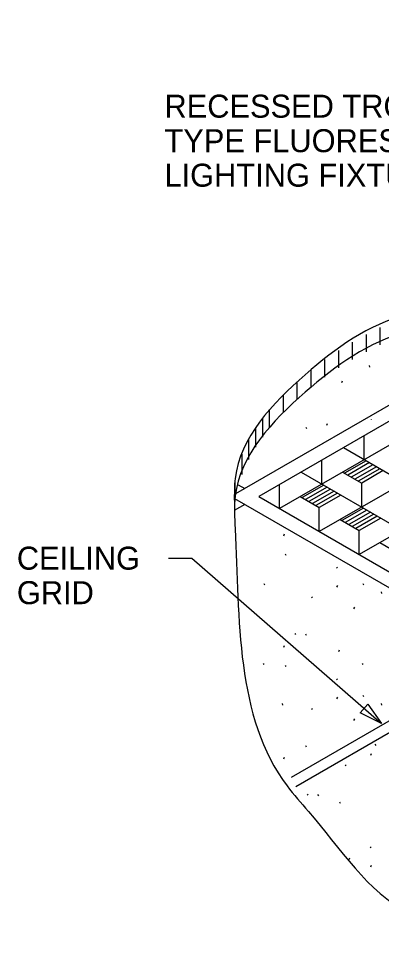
# Model space of a CAD drawing. Extents: x -12191 to -12144.8, y -12274.7 to -12230.3.
# Drawn here: x -12190.98 to -12180.47, y -12256.91 to -12230.27 of the extents above; entities that cross this region are included whole.
import ezdxf

# ---------------------------------------------------------------- set-up
doc = ezdxf.new("R2010")
doc.units = 0
for name, color, linetype in [('G-ANNO-TEXT', 7, 'Continuous'), ('G-DETL-LINE', 7, 'Continuous'), ('G-DETL-OTLN', 7, 'Continuous'), ('G-DETL-PATT', 7, 'Continuous')]:
    doc.layers.add(name, color=color, linetype=linetype)

msp = doc.modelspace()

# ---------------------------------------------------------------- linework, layer by layer
at = {"layer": 'G-ANNO-TEXT'}
for p, q in [((-12186.633, -12245.916), (-12185.966, -12245.916)), ((-12185.966, -12245.916), (-12180.475, -12250.707))]:
    msp.add_line(p, q, dxfattribs=at)
msp.add_lwpolyline([(-12180.867, -12250.143), (-12180.475, -12250.707), (-12181.087, -12250.394)], close=True, dxfattribs=at)
msp.add_lwpolyline([(-12180.867, -12250.143), (-12180.475, -12250.707), (-12181.087, -12250.394)], close=True, dxfattribs=at)
at = {"layer": 'G-DETL-LINE'}
for p, q in [((-12167.216, -12235.118), (-12183.425, -12244.476)), ((-12166.063, -12235.784), (-12182.272, -12245.142)), ((-12164.909, -12236.45), (-12181.118, -12245.808)), ((-12180.972, -12243.06), (-12180.972, -12242.367)), ((-12181.572, -12242.713), (-12174.052, -12247.055)), ((-12182.199, -12243.768), (-12182.199, -12243.075)), ((-12182.799, -12243.422), (-12175.278, -12247.763)), ((-12181.599, -12243.422), (-12181.045, -12243.741)), ((-12180.419, -12243.379), (-12181.045, -12243.741)), ((-12184.621, -12243.786), (-12184.425, -12243.899)), ((-12183.425, -12244.476), (-12183.425, -12243.783)), ((-12181.045, -12244.434), (-12181.045, -12243.741)), ((-12182.825, -12244.13), (-12182.272, -12244.449)), ((-12182.825, -12244.13), (-12182.272, -12244.449)), ((-12181.645, -12244.087), (-12182.272, -12244.449)), ((-12182.272, -12245.142), (-12182.272, -12244.449)), ((-12181.672, -12244.796), (-12181.118, -12245.115)), ((-12181.672, -12244.796), (-12181.118, -12245.115)), ((-12180.492, -12244.753), (-12181.118, -12245.115)), ((-12181.118, -12245.808), (-12181.118, -12245.115)), ((-12180.518, -12245.461), (-12179.965, -12245.781))]:
    msp.add_line(p, q, dxfattribs=at)
for points in [[(-12184.425, -12244.361), (-12184.732, -12244.538)], [(-12183.074, -12252.264), (-12176.905, -12248.702)], [(-12176.605, -12248.876), (-12182.947, -12252.538)]]:
    msp.add_lwpolyline(points, dxfattribs=at)
for points in [[(-12162.525, -12230.863), (-12165.604, -12230.321), (-12169.198, -12231.517), (-12170.826, -12232.527), (-12172.975, -12234.8), (-12175.893, -12236.119), (-12177.556, -12238.172), (-12179.732, -12238.849), (-12182.68, -12240.598), (-12184.707, -12243.604), (-12184.731, -12244.279)], [(-12162.525, -12231.37), (-12165.604, -12230.828), (-12169.198, -12232.024), (-12170.826, -12233.034), (-12172.975, -12235.307), (-12175.893, -12236.626), (-12177.556, -12238.679), (-12179.732, -12239.356), (-12182.68, -12241.105), (-12184.707, -12244.111), (-12184.707, -12245.062), (-12183.203, -12252.517), (-12182.588, -12253.253), (-12179.703, -12256.194), (-12174.789, -12256.716), (-12173.683, -12256.716), (-12171.38, -12255.642), (-12168.063, -12253.372), (-12164.408, -12252.329), (-12160.507, -12251.439), (-12159.14, -12248.077), (-12153.766, -12245.839), (-12151.853, -12243.292), (-12157.417, -12237.797), (-12158.233, -12233.96), (-12159.83, -12232.61), (-12162.157, -12231.504), (-12162.498, -12231.379)]]:
    msp.add_spline(points, degree=3, dxfattribs=at)
at = {"layer": 'G-DETL-OTLN'}
msp.add_lwpolyline([(-12184.723, -12244.189), (-12176.505, -12248.933), (-12159.496, -12239.113), (-12167.816, -12234.31), (-12184.694, -12244.054)], dxfattribs=at)
msp.add_lwpolyline([(-12167.816, -12234.771), (-12184.025, -12244.13), (-12176.505, -12248.471), (-12160.296, -12239.113)], close=True, dxfattribs=at)
at = {"layer": 'G-DETL-PATT'}
for p, q in [((-12180.518, -12239.227), (-12180.518, -12239.734)), ((-12180.918, -12239.432), (-12180.918, -12239.939)), ((-12181.318, -12239.653), (-12181.318, -12240.16)), ((-12181.718, -12239.895), (-12181.718, -12240.402)), ((-12182.118, -12240.163), (-12182.118, -12240.67)), ((-12180.828, -12240.332), (-12180.823, -12240.38)), ((-12182.518, -12240.464), (-12182.518, -12240.971)), ((-12182.918, -12240.803), (-12182.918, -12241.311)), ((-12181.62, -12240.822), (-12181.598, -12240.774)), ((-12183.318, -12241.178), (-12183.318, -12241.696)), ((-12183.718, -12241.608), (-12183.718, -12242.146)), ((-12183.918, -12241.855), (-12183.918, -12242.407)), ((-12180.761, -12241.899), (-12180.757, -12241.889)), ((-12184.118, -12242.136), (-12184.118, -12242.703)), ((-12182.661, -12242.124), (-12182.639, -12242.157)), ((-12182.057, -12242.061), (-12182.035, -12242.013)), ((-12184.318, -12242.468), (-12184.318, -12243.052)), ((-12184.518, -12242.898), (-12184.518, -12243.492)), ((-12180.919, -12243.091), (-12181.545, -12243.452)), ((-12180.819, -12243.148), (-12181.445, -12243.51)), ((-12180.719, -12243.206), (-12181.345, -12243.568)), ((-12180.619, -12243.264), (-12181.245, -12243.626)), ((-12180.519, -12243.322), (-12181.145, -12243.683)), ((-12184.718, -12243.683), (-12184.718, -12244.163)), ((-12182.145, -12243.799), (-12182.772, -12244.16)), ((-12182.045, -12243.856), (-12182.672, -12244.218)), ((-12181.945, -12243.914), (-12182.572, -12244.276)), ((-12181.845, -12243.972), (-12182.472, -12244.334)), ((-12181.745, -12244.03), (-12182.372, -12244.391)), ((-12180.992, -12244.465), (-12181.618, -12244.826)), ((-12180.892, -12244.522), (-12181.518, -12244.884)), ((-12180.792, -12244.58), (-12181.418, -12244.942)), ((-12180.692, -12244.638), (-12181.318, -12245)), ((-12180.592, -12244.696), (-12181.218, -12245.057)), ((-12183.297, -12245.264), (-12183.275, -12245.215)), ((-12183.264, -12245.791), (-12183.242, -12245.824)), ((-12181.777, -12246.174), (-12181.756, -12246.207)), ((-12183.881, -12246.653), (-12183.859, -12246.686)), ((-12181.76, -12246.758), (-12181.738, -12246.709)), ((-12181.011, -12246.653), (-12180.989, -12246.686)), ((-12182.501, -12247.037), (-12182.479, -12247.069)), ((-12180.477, -12246.893), (-12180.472, -12246.942)), ((-12181.269, -12247.384), (-12181.247, -12247.335)), ((-12182.979, -12248.099), (-12182.957, -12248.131)), ((-12182.671, -12248.111), (-12182.65, -12248.144)), ((-12183.297, -12248.499), (-12183.275, -12248.45)), ((-12181.706, -12248.623), (-12181.684, -12248.574)), ((-12183.901, -12248.968), (-12183.879, -12249.001)), ((-12183.264, -12249.027), (-12183.242, -12249.059)), ((-12181.031, -12248.968), (-12181.01, -12249.001)), ((-12181.777, -12249.41), (-12181.756, -12249.442)), ((-12181.76, -12249.993), (-12181.738, -12249.945)), ((-12181.011, -12249.889), (-12180.989, -12249.921)), ((-12183.347, -12250.129), (-12183.341, -12250.177)), ((-12180.477, -12250.129), (-12180.472, -12250.177)), ((-12182.501, -12250.272), (-12182.479, -12250.304)), ((-12181.269, -12250.619), (-12181.247, -12250.571)), ((-12180.66, -12251.31), (-12180.638, -12251.342)), ((-12182.671, -12251.347), (-12182.65, -12251.379)), ((-12180.779, -12251.626), (-12180.757, -12251.578)), ((-12183.297, -12251.734), (-12183.275, -12251.686)), ((-12181.52, -12251.905), (-12181.499, -12251.937)), ((-12182.627, -12252.756), (-12182.606, -12252.788)), ((-12182.32, -12252.768), (-12182.299, -12252.8)), ((-12181.69, -12252.98), (-12181.669, -12253.012)), ((-12180.796, -12254.278), (-12180.775, -12254.31)), ((-12181.408, -12254.65), (-12181.387, -12254.601)), ((-12180.779, -12254.862), (-12180.757, -12254.813))]:
    msp.add_line(p, q, dxfattribs=at)

# ---------------------------------------------------------------- texts
at = {"layer": 'G-ANNO-TEXT'}
for s, height, p in [('RECESSED TROFFER', 0.66667, (-12186.754, -12233.15)), ('TYPE FLUORESCENT', 0.66667, (-12186.754, -12234.15)), ('LIGHTING FIXTURE', 0.66667, (-12186.754, -12235.15)), ('CEILING', 0.6667, (-12191.027, -12246.249)), ('GRID', 0.6667, (-12191.027, -12247.249))]:
    msp.add_text(s, height=height, dxfattribs=at).set_placement(p)

doc.saveas('drawing.dxf')
